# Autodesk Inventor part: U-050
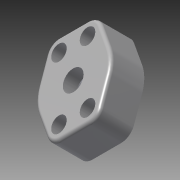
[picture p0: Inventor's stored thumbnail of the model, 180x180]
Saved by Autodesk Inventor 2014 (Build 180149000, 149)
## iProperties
Created: 2011-01
Part Number: U-050
Material: Steel
Document SubType Name: Modeling
Designer: deckm
Density: 7.85 g/cm^3
Description: FLARED FLANGE SAE WITH CLEARANCE HOLES
Mass: 259.498 g
Surface Area: 100.719 cm^2
Volume: 33.0571 cm^3
Appearance: Steel
Author: deckm
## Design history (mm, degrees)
derived "union_cap.ipt"
body "Solid1"
feature "Solid1::union_cap.ipt"
tag "TaggingFeature1"
other parameters: "d1" = 54.864, "d3" = 19.10263, "d25" = 17.526, "FilletTop" = 2, "d27" = 9.525, "d28" = 37 deg, "d29" = 20.574, "d30" = 6.35, "FilletCorners" = 8.382, "FilletEnds" = 22.987, "d8" = 20.574, "d9" = 0, "d12" = 9.525, "d21" = 17.526, "d24" = 38.1
